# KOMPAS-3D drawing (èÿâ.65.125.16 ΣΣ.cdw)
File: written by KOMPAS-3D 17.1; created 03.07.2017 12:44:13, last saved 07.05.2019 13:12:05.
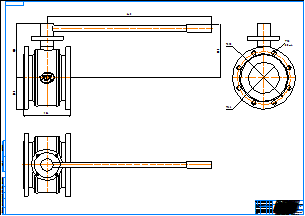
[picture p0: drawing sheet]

Sheet 1: A0, landscape

Title block, sheet 1: name: КШГ.65.125.16 фф; material: Внимание! Данный продукт является объектом авторского права ООО «Торговый Дом АДЛ». / Запрещается изменение, копирование, распространение / (в том числе путем копирования на другие сайты и ресурсы в Интернете) / или любое иное использование информации и объектов без предварительного / согласия правообладателя (ООО «Торговый Дом АДЛ»).; sheets: 1; organisation: ООО "Торговый дом АДЛ"; sheet format: A0; stored path: C:\Users\kka\KOMPAS_Work\!Trash\СС02 СС03 ФФ Смотровые стекла\СС01.cdw

Views: Спереди 1, Проекционный вид 2, Проекционный вид 3
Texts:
  Klimkovich
  ADL
Dimensions and other numbers on the sheet: 645; 209; 186; 213; 123; 210; 122; 18; 8 Отв.; 1:1; 1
